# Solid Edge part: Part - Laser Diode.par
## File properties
Author: hhakima
Template: Normal.par
Last saved by: hhakima
Revision: 7
Application: Solid Edge
Accuracy: 0.990
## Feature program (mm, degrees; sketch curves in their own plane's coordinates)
sketch for "unnamed Protrusion 1" plane through (0, 0, 0) normal (0, 0, 1) x-axis (1, 0, 0)
  circle centre (0, 0) radius 4.5
extrude "unnamed Protrusion 1" add finite 1.5 along +normal
sketch for "ExtrudedProtrusion_2" plane through (0, 0, 1.5) normal (0, 0, 1) x-axis (1, 0, 0)
  circle centre (0, 0) radius 3.3
extrude "ExtrudedProtrusion_2" add finite 3.4 along +normal
sketch for "ExtrudedCutout_1" plane through (0, 0, 4.9) normal (0, 0, 1) x-axis (1, 0, 0)
  circle centre (0, 0) radius 1.5
extrude "ExtrudedCutout_1" cut finite 1 along -normal
sketch for "pin1" plane through (0, 0, 0) normal (0, 0, -1) x-axis (1, 0, 0)
  circle centre (-2, 0) radius 0.25
extrude "pin1" add finite 7 along +normal
mirror "unnamed Mirror 1" of "pin1"
pattern "unnamed Pattern 1"
sketch for "ExtrudedProtrusion_5" plane through (0, 0, 0) normal (0, 0, -1) x-axis (1, 0, 0)
  circle centre (0, -2) radius 0.25
extrude "ExtrudedProtrusion_5" add finite 7 along +normal
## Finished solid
Body 1: solid body, 13 faces, 12 edges, 0 vertices.
  Faces by surface: plane 7, cylinder 6
  Edges by curve: circle 12
Bounding box of the edges (mm): 9.000 x 9.000 x 11.900, from (-4.5, -4.5, -7) to (4.5, 4.5, 4.9).
Cylindrical faces by radius (mm): R0.25 x3, R1.5 x1, R3.3 x1, R4.5 x1
Planar faces by outward normal: +z 3, -z 4
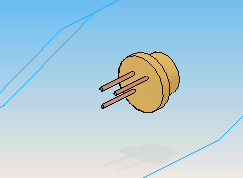
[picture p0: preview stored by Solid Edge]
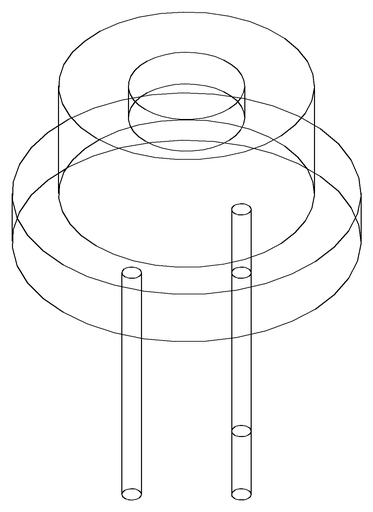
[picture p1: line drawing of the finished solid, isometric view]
